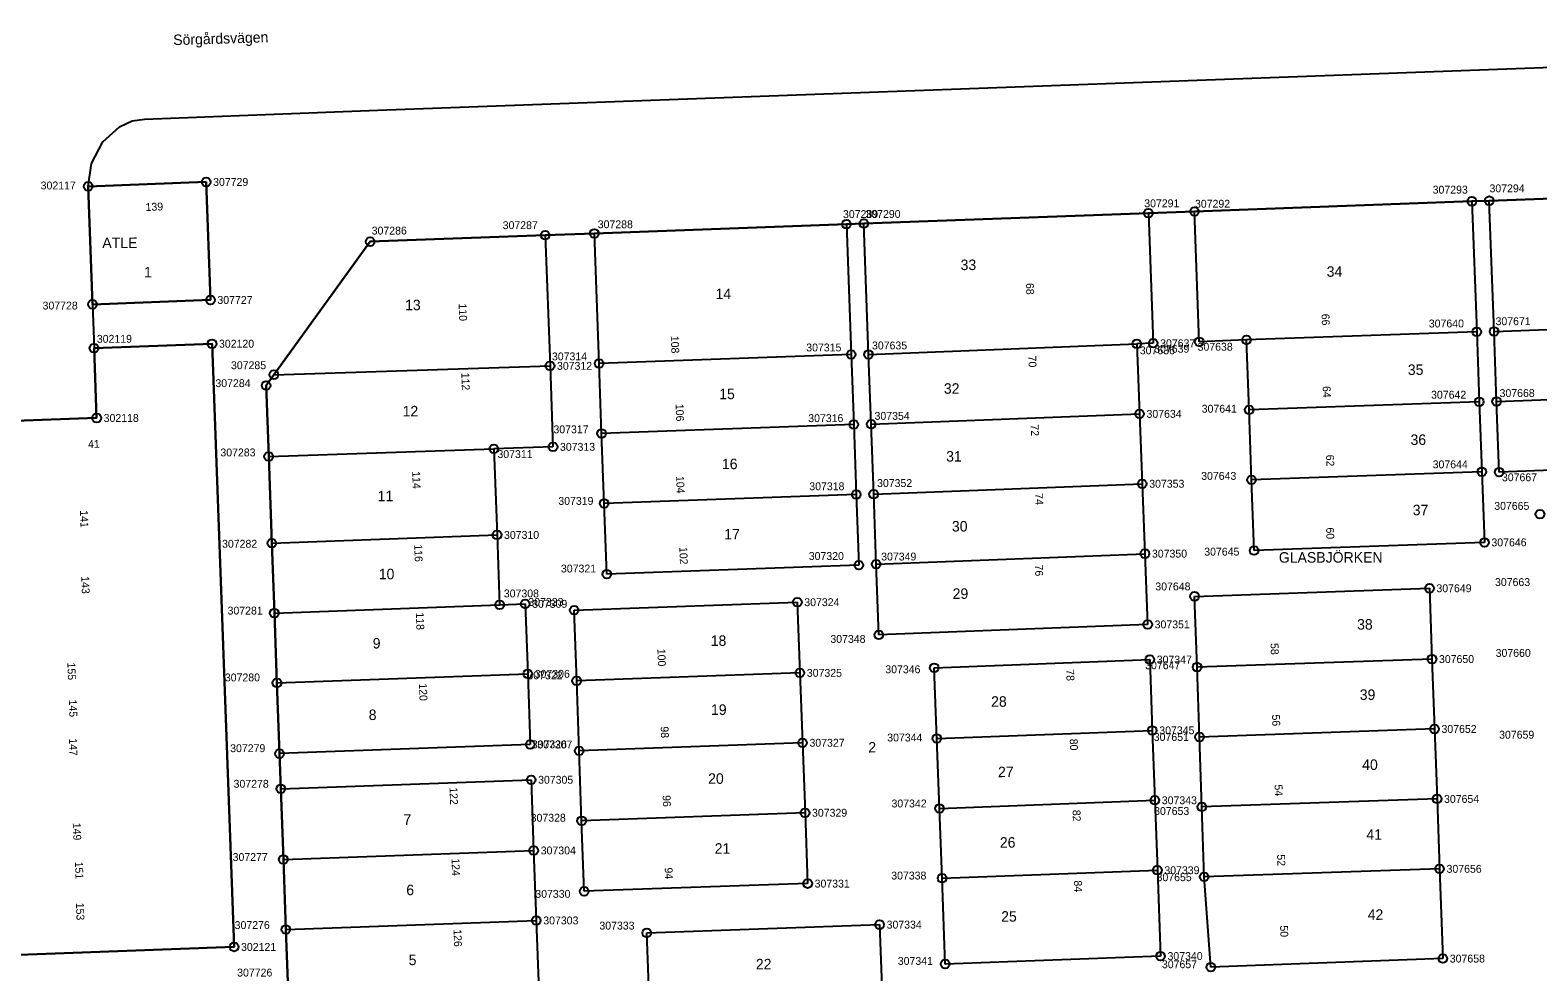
# Model space of a CAD drawing. Extents: x 141995 to 152570, y 6580184 to 6586000.
# Drawn here: x 142575.6 to 142748, y 6585258.5 to 6585366.1 of the extents above; entities that cross this region are included whole.
import ezdxf

# ---------------------------------------------------------------- set-up
doc = ezdxf.new("R2010")
doc.units = 0
for name, color, linetype in [('Level 10', 7, 'Continuous'), ('Level 13', 7, 'Continuous'), ('Level 42', 7, 'Continuous'), ('Level 5', 7, 'Continuous'), ('Level 50', 7, 'Continuous'), ('Level 51', 7, 'Continuous'), ('Level 53', 7, 'Continuous'), ('Level 54', 7, 'Continuous'), ('Level 55', 7, 'Continuous'), ('Level 6', 7, 'Continuous'), ('Level 7', 7, 'Continuous')]:
    doc.layers.add(name, color=color, linetype=linetype)

msp = doc.modelspace()

# ---------------------------------------------------------------- linework, layer by layer
at = {"layer": 'Level 10'}
for centre in [(142582.19, 6585348.25), (142595.68, 6585348.75), (142740.42, 6585346.54), (142742.4, 6585346.61), (142668.89, 6585343.92), (142670.88, 6585343.99), (142703.42, 6585345.18), (142708.69, 6585345.38), (142634.45, 6585342.66), (142640.07, 6585342.87), (142614.44, 6585341.93), (142582.68, 6585334.76), (142596.17, 6585335.26), (142596.35, 6585330.26), (142702.09, 6585330.24), (142703.97, 6585330.31), (142709.24, 6585330.49), (142714.65, 6585330.69), (142740.97, 6585331.62), (142742.95, 6585331.67), (142582.86, 6585329.76), (142669.43, 6585329.02), (142671.42, 6585329.04), (142603.43, 6585326.72), (142635, 6585327.73), (142640.61, 6585328), (142602.53, 6585325.48), (142741.26, 6585323.63), (142743.24, 6585323.67), (142583.16, 6585321.77), (142702.41, 6585322.24), (142714.94, 6585322.69), (142640.9, 6585320.01), (142669.73, 6585321.03), (142671.72, 6585321.05), (142628.57, 6585318.24), (142635.34, 6585318.47), (142602.83, 6585317.37), (142715.22, 6585314.7), (142741.55, 6585315.63), (142743.54, 6585315.59), (142670.02, 6585313.03), (142672.01, 6585313.05), (142702.72, 6585314.25), (142641.2, 6585312.01), (142748.2, 6585310.77), (142628.94, 6585308.4), (142603.19, 6585307.46), (142703.03, 6585306.26), (142715.51, 6585306.61), (142741.85, 6585307.55), (142670.32, 6585304.95), (142672.3, 6585305.06), (142641.49, 6585303.93), (142708.71, 6585301.38), (142735.56, 6585302.3), (142603.48, 6585299.47), (142629.24, 6585300.41), (142632.16, 6585300.51), (142637.76, 6585299.8), (142663.28, 6585300.71), (142703.34, 6585298.17), (142672.6, 6585296.97), (142703.58, 6585294.15), (142735.85, 6585294.21), (142632.45, 6585292.52), (142663.57, 6585292.63), (142678.94, 6585293.22), (142708.99, 6585293.3), (142603.78, 6585291.48), (142638.05, 6585291.72), (142703.87, 6585286.06), (142709.26, 6585285.3), (142736.14, 6585286.22), (142632.74, 6585284.44), (142638.33, 6585283.72), (142663.87, 6585284.64), (142679.24, 6585285.14), (142604.07, 6585283.4), (142632.84, 6585280.41), (142604.22, 6585279.39), (142679.54, 6585277.14), (142704.16, 6585278.07), (142709.53, 6585277.31), (142736.43, 6585278.22), (142638.62, 6585275.73), (142664.16, 6585276.64), (142633.13, 6585272.33), (142604.51, 6585271.31), (142704.45, 6585270.07), (142736.72, 6585270.23), (142664.46, 6585268.54), (142679.83, 6585269.15), (142709.8, 6585269.31), (142638.9, 6585267.66), (142604.8, 6585263.31), (142633.43, 6585264.33), (142646.06, 6585262.9), (142672.69, 6585263.85), (142598.87, 6585261.3), (142704.81, 6585260.26), (142737.09, 6585259.97), (142680.19, 6585259.35), (142710.56, 6585259)]:
    msp.add_circle(centre, 0.5, dxfattribs=at)
at = {"layer": 'Level 13'}
for points in [[(142615.3, 6585356.97), (142865.18, 6585366.11)], [(142588.65, 6585355.94), (142615.3, 6585356.97)], [(142582.19, 6585348.25), (142582.56, 6585350.85), (142583.87, 6585353.35), (142585.78, 6585355.05), (142586.59, 6585355.43)], [(142586.59, 6585355.43), (142587.23, 6585355.74), (142588.65, 6585355.94)], [(142582.68, 6585334.76), (142582.86, 6585329.76)]]:
    msp.add_lwpolyline(points, dxfattribs=at)
at = {"layer": 'Level 5'}
for points in [[(142582.19, 6585348.25), (142595.68, 6585348.75)], [(142582.68, 6585334.76), (142582.19, 6585348.25)], [(142595.68, 6585348.75), (142596.17, 6585335.26)], [(142708.69, 6585345.38), (142740.42, 6585346.54)], [(142740.42, 6585346.54), (142742.4, 6585346.61)], [(142742.4, 6585346.61), (142772.24, 6585347.7)], [(142670.88, 6585343.99), (142703.42, 6585345.18)], [(142703.42, 6585345.18), (142708.69, 6585345.38)], [(142634.45, 6585342.66), (142640.07, 6585342.87)], [(142640.07, 6585342.87), (142668.89, 6585343.92)], [(142668.89, 6585343.92), (142670.88, 6585343.99)], [(142603.43, 6585326.72), (142614.44, 6585341.93)], [(142614.44, 6585341.93), (142634.45, 6585342.66)], [(142596.17, 6585335.26), (142582.68, 6585334.76)], [(142582.86, 6585329.76), (142596.35, 6585330.26)], [(142583.16, 6585321.77), (142582.86, 6585329.76)], [(142596.35, 6585330.26), (142598.87, 6585261.3)], [(142602.53, 6585325.48), (142603.43, 6585326.72)], [(142602.83, 6585317.37), (142602.53, 6585325.48)], [(142538.68, 6585320.14), (142583.16, 6585321.77)], [(142603.19, 6585307.46), (142602.83, 6585317.37)], [(142603.48, 6585299.47), (142603.19, 6585307.46)], [(142603.78, 6585291.48), (142603.48, 6585299.47)], [(142604.07, 6585283.4), (142603.78, 6585291.48)], [(142604.22, 6585279.39), (142604.07, 6585283.4)], [(142604.51, 6585271.31), (142604.22, 6585279.39)], [(142604.8, 6585263.31), (142604.51, 6585271.31)], [(142605.1, 6585255.32), (142604.8, 6585263.31)], [(142598.87, 6585261.3), (142557.9, 6585259.8)]]:
    msp.add_lwpolyline(points, dxfattribs=at)
at = {"layer": 'Level 6'}
for points in [[(142595.68, 6585348.75), (142582.19, 6585348.25), (142582.68, 6585334.76), (142596.17, 6585335.26)], [(142539.64, 6585294.16), (142557.9, 6585259.8), (142598.87, 6585261.3), (142596.35, 6585330.26), (142582.86, 6585329.76), (142583.16, 6585321.77), (142538.68, 6585320.14)]]:
    msp.add_lwpolyline(points, close=True, dxfattribs=at)
msp.add_lwpolyline([(142772.24, 6585347.7), (142742.4, 6585346.61), (142740.42, 6585346.54), (142708.69, 6585345.38), (142703.42, 6585345.18), (142670.88, 6585343.99), (142668.89, 6585343.92), (142640.07, 6585342.87), (142634.45, 6585342.66), (142614.44, 6585341.93), (142603.43, 6585326.72), (142602.53, 6585325.48), (142602.83, 6585317.37), (142603.19, 6585307.46), (142603.48, 6585299.47), (142603.78, 6585291.48), (142604.07, 6585283.4), (142604.22, 6585279.39), (142604.51, 6585271.31), (142604.8, 6585263.31), (142605.1, 6585255.32)], dxfattribs=at)
at = {"layer": 'Level 7'}
for points in [[(142740.42, 6585346.54), (142740.97, 6585331.62)], [(142742.95, 6585331.67), (142742.4, 6585346.61)], [(142703.42, 6585345.18), (142703.97, 6585330.31)], [(142709.24, 6585330.49), (142708.69, 6585345.38)], [(142640.61, 6585328), (142640.07, 6585342.87)], [(142668.89, 6585343.92), (142669.43, 6585329.02)], [(142671.42, 6585329.04), (142670.88, 6585343.99)], [(142634.45, 6585342.66), (142635, 6585327.73)], [(142742.95, 6585331.67), (142769.26, 6585332.66)], [(142714.65, 6585330.69), (142709.24, 6585330.49)], [(142740.97, 6585331.62), (142714.65, 6585330.69)], [(142714.94, 6585322.69), (142714.65, 6585330.69)], [(142740.97, 6585331.62), (142741.26, 6585323.63)], [(142743.24, 6585323.67), (142742.95, 6585331.67)], [(142669.43, 6585329.02), (142640.61, 6585328)], [(142669.43, 6585329.02), (142669.73, 6585321.03)], [(142671.42, 6585329.04), (142702.09, 6585330.24)], [(142671.72, 6585321.05), (142671.42, 6585329.04)], [(142703.97, 6585330.31), (142702.09, 6585330.24)], [(142702.09, 6585330.24), (142702.41, 6585322.24)], [(142603.43, 6585326.72), (142635, 6585327.73)], [(142635, 6585327.73), (142635.34, 6585318.47)], [(142640.9, 6585320.01), (142640.61, 6585328)], [(142743.24, 6585323.67), (142769.56, 6585324.66)], [(142671.72, 6585321.05), (142702.41, 6585322.24)], [(142702.41, 6585322.24), (142702.72, 6585314.25)], [(142741.26, 6585323.63), (142714.94, 6585322.69)], [(142715.22, 6585314.7), (142714.94, 6585322.69)], [(142741.26, 6585323.63), (142741.55, 6585315.63)], [(142743.54, 6585315.59), (142743.24, 6585323.67)], [(142669.73, 6585321.03), (142640.9, 6585320.01)], [(142669.73, 6585321.03), (142670.02, 6585313.03)], [(142672.01, 6585313.05), (142671.72, 6585321.05)], [(142641.2, 6585312.01), (142640.9, 6585320.01)], [(142602.83, 6585317.37), (142628.57, 6585318.24)], [(142635.34, 6585318.47), (142628.57, 6585318.24)], [(142628.57, 6585318.24), (142628.94, 6585308.4)], [(142741.55, 6585315.63), (142715.22, 6585314.7)], [(142741.55, 6585315.63), (142741.85, 6585307.55)], [(142769.87, 6585316.58), (142743.54, 6585315.59)], [(142672.01, 6585313.05), (142702.72, 6585314.25)], [(142702.72, 6585314.25), (142703.03, 6585306.26)], [(142715.51, 6585306.61), (142715.22, 6585314.7)], [(142670.02, 6585313.03), (142641.2, 6585312.01)], [(142641.49, 6585303.93), (142641.2, 6585312.01)], [(142670.02, 6585313.03), (142670.32, 6585304.95)], [(142672.3, 6585305.06), (142672.01, 6585313.05)], [(142603.19, 6585307.46), (142628.94, 6585308.4)], [(142628.94, 6585308.4), (142629.24, 6585300.41)], [(142741.85, 6585307.55), (142715.51, 6585306.61)], [(142670.32, 6585304.95), (142641.49, 6585303.93)], [(142672.3, 6585305.06), (142703.03, 6585306.26)], [(142672.6, 6585296.97), (142672.3, 6585305.06)], [(142703.03, 6585306.26), (142703.34, 6585298.17)], [(142708.71, 6585301.38), (142735.56, 6585302.3)], [(142708.99, 6585293.3), (142708.71, 6585301.38)], [(142735.56, 6585302.3), (142735.85, 6585294.21)], [(142603.48, 6585299.47), (142629.24, 6585300.41)], [(142629.24, 6585300.41), (142632.16, 6585300.51)], [(142632.16, 6585300.51), (142632.45, 6585292.52)], [(142637.76, 6585299.8), (142663.28, 6585300.71)], [(142638.05, 6585291.72), (142637.76, 6585299.8)], [(142663.28, 6585300.71), (142663.57, 6585292.63)], [(142703.34, 6585298.17), (142672.6, 6585296.97)], [(142678.94, 6585293.22), (142703.58, 6585294.15)], [(142679.24, 6585285.14), (142678.94, 6585293.22)], [(142703.58, 6585294.15), (142703.87, 6585286.06)], [(142735.85, 6585294.21), (142708.99, 6585293.3)], [(142709.26, 6585285.3), (142708.99, 6585293.3)], [(142735.85, 6585294.21), (142736.14, 6585286.22)], [(142603.78, 6585291.48), (142632.45, 6585292.52)], [(142632.45, 6585292.52), (142632.74, 6585284.44)], [(142663.57, 6585292.63), (142638.05, 6585291.72)], [(142638.33, 6585283.72), (142638.05, 6585291.72)], [(142663.57, 6585292.63), (142663.87, 6585284.64)], [(142679.24, 6585285.14), (142703.87, 6585286.06)], [(142703.87, 6585286.06), (142704.16, 6585278.07)], [(142736.14, 6585286.22), (142709.26, 6585285.3)], [(142736.14, 6585286.22), (142736.43, 6585278.22)], [(142632.74, 6585284.44), (142604.07, 6585283.4)], [(142663.87, 6585284.64), (142638.33, 6585283.72)], [(142663.87, 6585284.64), (142664.16, 6585276.64)], [(142679.54, 6585277.14), (142679.24, 6585285.14)], [(142709.53, 6585277.31), (142709.26, 6585285.3)], [(142638.62, 6585275.73), (142638.33, 6585283.72)], [(142604.22, 6585279.39), (142632.84, 6585280.41)], [(142632.84, 6585280.41), (142633.13, 6585272.33)], [(142679.54, 6585277.14), (142704.16, 6585278.07)], [(142704.16, 6585278.07), (142704.45, 6585270.07)], [(142736.43, 6585278.22), (142709.53, 6585277.31)], [(142709.8, 6585269.31), (142709.53, 6585277.31)], [(142736.43, 6585278.22), (142736.72, 6585270.23)], [(142664.16, 6585276.64), (142638.62, 6585275.73)], [(142638.9, 6585267.66), (142638.62, 6585275.73)], [(142664.16, 6585276.64), (142664.46, 6585268.54)], [(142679.83, 6585269.15), (142679.54, 6585277.14)], [(142604.51, 6585271.31), (142633.13, 6585272.33)], [(142633.13, 6585272.33), (142633.43, 6585264.33)], [(142664.46, 6585268.54), (142638.9, 6585267.66)], [(142679.83, 6585269.15), (142704.45, 6585270.07)], [(142680.19, 6585259.35), (142679.83, 6585269.15)], [(142704.45, 6585270.07), (142704.81, 6585260.26)], [(142736.72, 6585270.23), (142709.8, 6585269.31)], [(142710.56, 6585259), (142709.8, 6585269.31)], [(142736.72, 6585270.23), (142737.09, 6585259.97)], [(142604.8, 6585263.31), (142633.43, 6585264.33)], [(142633.43, 6585264.33), (142633.72, 6585256.34)], [(142646.06, 6585262.9), (142672.69, 6585263.85)], [(142672.69, 6585263.85), (142672.98, 6585255.77)], [(142646.37, 6585254.82), (142646.06, 6585262.9)], [(142704.81, 6585260.26), (142680.19, 6585259.35)], [(142737.09, 6585259.97), (142710.56, 6585259)]]:
    msp.add_lwpolyline(points, dxfattribs=at)

# ---------------------------------------------------------------- texts
at = {"layer": 'Level 42'}
msp.add_text('Sörgårdsvägen', height=1.2, rotation=1.8005, dxfattribs=at).set_placement((142591.93, 6585364.39))
at = {"layer": 'Level 50'}
for s, rotation, p in [('ATLE', 0.0522, (142583.81, 6585341.2)), ('GLASBJÖRKEN', 0.0514, (142718.34, 6585305.23))]:
    msp.add_text(s, height=1.2, rotation=rotation, dxfattribs=at).set_placement(p)
at = {"layer": 'Level 51'}
for s, rotation, p in [('33', 0.0514, (142681.95, 6585338.68)), ('34', 0.0493, (142723.81, 6585337.91)), ('14', 0.0514, (142653.93, 6585335.36)), ('13', 0.0522, (142618.43, 6585334.09)), ('35', 0.0493, (142733.09, 6585326.69)), ('32', 0.0514, (142680.04, 6585324.54)), ('15', 0.0514, (142654.35, 6585323.92)), ('12', 0.0514, (142618.15, 6585321.95)), ('36', 0.0493, (142733.4, 6585318.69)), ('16', 0.0514, (142654.66, 6585315.92)), ('31', 0.0514, (142680.3, 6585316.79)), ('11', 0.0514, (142615.29, 6585312.25)), ('37', 0.0493, (142733.65, 6585310.65)), ('30', 0.0514, (142680.96, 6585308.79)), ('17', 0.0514, (142654.92, 6585307.88)), ('10', 0.0514, (142615.42, 6585303.33)), ('29', 0.0514, (142681.04, 6585301.09)), ('38', 0.0514, (142727.29, 6585297.58)), ('9', 0.0514, (142614.73, 6585295.42)), ('18', 0.0514, (142653.38, 6585295.72)), ('28', 0.0514, (142685.44, 6585288.76)), ('39', 0.0514, (142727.59, 6585289.54)), ('8', 0.0514, (142614.27, 6585287.24)), ('19', 0.0514, (142653.41, 6585287.83)), ('2', 0.0514, (142671.4, 6585283.53)), ('40', 0.0514, (142727.87, 6585281.54)), ('20', 0.0514, (142653.08, 6585279.95)), ('27', 0.0514, (142686.23, 6585280.71)), ('7', 0.0514, (142618.24, 6585275.26)), ('26', 0.0514, (142686.44, 6585272.65)), ('41', 0.0514, (142728.35, 6585273.55)), ('21', 0.0514, (142653.83, 6585271.96)), ('6', 0.0514, (142618.57, 6585267.22)), ('25', 0.0514, (142686.59, 6585264.19)), ('42', 0.0514, (142728.5, 6585264.4)), ('5', 0.0514, (142618.84, 6585259.22)), ('22', 0.0514, (142658.54, 6585258.74))]:
    msp.add_text(s, height=1.2, rotation=rotation, dxfattribs=at).set_placement(p)
msp.add_text('1', height=1.2, dxfattribs=at).set_placement((142588.58, 6585337.85))
at = {"layer": 'Level 53'}
for s, rotation, p in [('302117', 0.0526, (142576.76, 6585347.9)), ('307729', 0.0522, (142596.48, 6585348.3)), ('307293', 0.0493, (142735.93, 6585347.42)), ('307294', 0.0493, (142742.43, 6585347.57)), ('307291', 0.0493, (142702.95, 6585345.86)), ('307292', 0.0493, (142708.75, 6585345.81)), ('307289', 0.0514, (142668.5, 6585344.63)), ('307290', 0.0514, (142671.07, 6585344.64)), ('307286', 0.0522, (142614.61, 6585342.74)), ('307287', 0.0514, (142629.59, 6585343.36)), ('307288', 0.0514, (142640.46, 6585343.46)), ('307728', 0.0522, (142576.98, 6585334.17)), ('307727', 0.0522, (142596.97, 6585334.81)), ('307640', 0.0493, (142735.49, 6585332.12)), ('307671', 0.0493, (142743.12, 6585332.38)), ('302119', 0.0522, (142583.18, 6585330.37)), ('302120', 0.0522, (142597.15, 6585329.81)), ('307637', 0.0499, (142704.77, 6585329.86)), ('307314', 0.0514, (142635.22, 6585328.36)), ('307315', 0.0514, (142664.3, 6585329.38)), ('307635', 0.0514, (142671.82, 6585329.61)), ('307636', 0.0514, (142702.44, 6585329.05)), ('307639', 0.0493, (142704.09, 6585329.23)), ('307638', 0.0493, (142709.05, 6585329.46)), ('307285', 0.0522, (142598.52, 6585327.35)), ('307312', 0.0514, (142635.8, 6585327.28)), ('307284', 0.0522, (142596.74, 6585325.3)), ('307642', 0.0493, (142735.75, 6585323.98)), ('307668', 0.0493, (142743.58, 6585324.17)), ('302118', 0.0522, (142583.96, 6585321.32)), ('307316', 0.0514, (142664.53, 6585321.3)), ('307354', 0.0514, (142672.11, 6585321.56)), ('307634', 0.0514, (142703.21, 6585321.79)), ('307641', 0.0514, (142709.52, 6585322.38)), ('307317', 0.0514, (142635.39, 6585320.02)), ('307313', 0.0514, (142636.14, 6585318.02)), ('307283', 0.0522, (142597.31, 6585317.38)), ('307311', 0.0514, (142628.99, 6585317.19)), ('307644', 0.0493, (142735.93, 6585316.02)), ('307643', 0.0514, (142709.46, 6585314.7)), ('307667', 0.0493, (142743.85, 6585314.54)), ('307318', 0.0514, (142664.65, 6585313.51)), ('307352', 0.0514, (142672.4, 6585313.88)), ('307353', 0.0514, (142703.52, 6585313.8)), ('307319', 0.0514, (142635.95, 6585311.84)), ('307665', 0.0493, (142742.97, 6585311.27)), ('307310', 0.0514, (142629.74, 6585307.95)), ('307282', 0.0522, (142597.5, 6585306.94)), ('307350', 0.0514, (142703.83, 6585305.81)), ('307645', 0.0514, (142709.81, 6585306.04)), ('307646', 0.0493, (142742.65, 6585307.1)), ('307321', 0.0514, (142636.25, 6585304.11)), ('307320', 0.0514, (142664.59, 6585305.54)), ('307349', 0.0514, (142672.87, 6585305.48)), ('307663', 0.0493, (142743.06, 6585302.56)), ('307308', 0.0514, (142629.72, 6585301.26)), ('307648', 0.0514, (142704.22, 6585302.06)), ('307649', 0.0514, (142736.36, 6585301.85)), ('307281', 0.0522, (142598.13, 6585299.3)), ('307323', 0.0514, (142632.52, 6585300.29)), ('307309', 0.0514, (142632.96, 6585300.07)), ('307324', 0.0514, (142664.08, 6585300.26)), ('307351', 0.0514, (142704.14, 6585297.72)), ('307348', 0.0514, (142667.06, 6585296.06)), ('307347', 0.0514, (142704.38, 6585293.7)), ('307650', 0.0514, (142736.65, 6585293.76)), ('307660', 0.0514, (142743.13, 6585294.46)), ('307322', 0.0514, (142632.42, 6585291.9)), ('307306', 0.0514, (142633.25, 6585292.07)), ('307325', 0.0514, (142664.37, 6585292.18)), ('307346', 0.0514, (142673.34, 6585292.59)), ('307647', 0.0514, (142703.06, 6585293.05)), ('307280', 0.0519, (142597.82, 6585291.66)), ('307345', 0.0514, (142704.67, 6585285.61)), ('307652', 0.0514, (142736.94, 6585285.77)), ('307659', 0.0514, (142743.53, 6585285.11)), ('307279', 0.0514, (142598.43, 6585283.57)), ('307326', 0.0514, (142632.92, 6585284.01)), ('307307', 0.0514, (142633.54, 6585283.99)), ('307327', 0.0514, (142664.67, 6585284.19)), ('307344', 0.0514, (142673.56, 6585284.79)), ('307651', 0.0514, (142704.04, 6585284.85)), ('307305', 0.0514, (142633.64, 6585279.96)), ('307278', 0.0514, (142598.82, 6585279.5)), ('307342', 0.0514, (142674.05, 6585277.25)), ('307653', 0.0514, (142704.08, 6585276.39)), ('307343', 0.0514, (142704.96, 6585277.62)), ('307654', 0.0514, (142737.23, 6585277.77)), ('307328', 0.0514, (142632.79, 6585275.62)), ('307329', 0.0514, (142664.96, 6585276.19)), ('307277', 0.0514, (142598.71, 6585271.13)), ('307304', 0.0514, (142633.94, 6585271.88)), ('307339', 0.0514, (142705.25, 6585269.62)), ('307656', 0.0514, (142737.52, 6585269.78)), ('307331', 0.0514, (142665.26, 6585268.09)), ('307338', 0.0514, (142674.02, 6585269.01)), ('307655', 0.0514, (142704.36, 6585268.82)), ('307330', 0.0514, (142633.32, 6585266.92)), ('307276', 0.0514, (142598.94, 6585263.35)), ('307303', 0.0514, (142634.23, 6585263.88)), ('307333', 0.0514, (142640.65, 6585263.29)), ('307334', 0.0514, (142673.49, 6585263.4)), ('302121', 0.0514, (142599.67, 6585260.85)), ('307341', 0.0514, (142674.77, 6585259.25)), ('307340', 0.0514, (142705.61, 6585259.81)), ('307658', 0.0514, (142737.89, 6585259.52)), ('307726', 0.0514, (142599.23, 6585257.92)), ('307657', 0.0514, (142704.97, 6585258.87))]:
    msp.add_text(s, height=0.9, rotation=rotation, dxfattribs=at).set_placement(p)
at = {"layer": 'Level 54'}
for s, rotation, p in [('139', 2.2212, (142588.77, 6585345.43)), ('68', 272.0969, (142689.42, 6585337.19)), ('110', 272.0369, (142624.55, 6585334.85)), ('66', 272.072, (142723.22, 6585333.67)), ('108', 272.0679, (142648.81, 6585331.15)), ('70', 272.0969, (142689.69, 6585328.88)), ('112', 272.0369, (142624.86, 6585326.93)), ('64', 272.072, (142723.35, 6585325.41)), ('106', 272.0689, (142649.36, 6585323.37)), ('72', 272.0969, (142689.97, 6585321.02)), ('62', 272.0689, (142723.74, 6585317.56)), ('114', 272.1489, (142619.24, 6585315.67)), ('104', 272.0689, (142649.42, 6585315.13)), ('74', 272.0969, (142690.47, 6585313.15)), ('141', 272.0806, (142581.25, 6585311.21)), ('60', 272.0689, (142723.74, 6585309.24)), ('116', 272.1489, (142619.47, 6585307.31)), ('102', 272.0689, (142649.79, 6585307.01)), ('76', 272.0969, (142690.44, 6585305)), ('143', 272.0806, (142581.4, 6585303.67)), ('118', 272.1489, (142619.66, 6585299.53)), ('100', 272.0529, (142647.28, 6585295.37)), ('58', 272.0939, (142717.39, 6585296.03)), ('155', 272.0856, (142579.81, 6585293.8)), ('78', 272.0839, (142694.02, 6585293.03)), ('120', 272.1489, (142620.01, 6585291.42)), ('145', 272.0856, (142579.98, 6585289.57)), ('56', 272.0939, (142717.56, 6585287.86)), ('98', 272.0529, (142647.65, 6585286.5)), ('147', 272.0856, (142579.99, 6585285.14)), ('80', 272.0839, (142694.43, 6585285.09)), ('122', 272.0899, (142623.51, 6585279.54)), ('54', 272.0939, (142717.85, 6585279.86)), ('96', 272.0529, (142647.88, 6585278.64)), ('82', 272.0839, (142694.75, 6585276.96)), ('149', 272.0856, (142580.43, 6585275.48)), ('151', 272.0856, (142580.68, 6585271.04)), ('124', 272.0899, (142623.74, 6585271.42)), ('94', 272.0529, (142648.11, 6585270.37)), ('52', 272.0939, (142718.14, 6585271.87)), ('84', 272.0839, (142694.91, 6585268.89)), ('153', 272.0856, (142580.79, 6585266.34)), ('50', 272.0939, (142718.48, 6585263.75)), ('126', 272.0899, (142623.97, 6585263.31))]:
    msp.add_text(s, height=0.9, rotation=rotation, dxfattribs=at).set_placement(p)
at = {"layer": 'Level 55'}
msp.add_text('41', height=0.9, rotation=2.0972, dxfattribs=at).set_placement((142582.19, 6585318.33))

doc.saveas('drawing.dxf')
